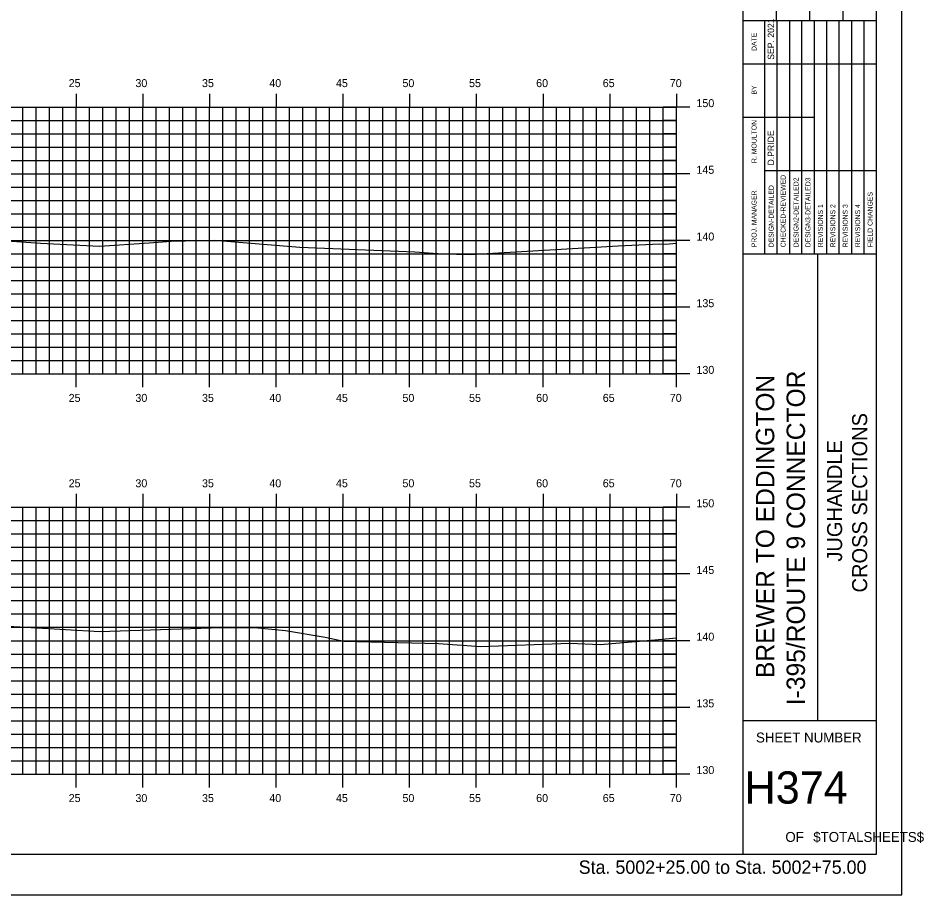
# Model space of a CAD drawing. Extents: x 851417 to 851588, y 365876 to 365986.
# Drawn here: x 851520.6 to 851588.4, y 365875.8 to 365941.5 of the extents above; entities that cross this region are included whole.
import ezdxf

# ---------------------------------------------------------------- set-up
doc = ezdxf.new("R2010")
doc.units = 0
for name, color, linetype in [('BORDER', 7, 'Continuous'), ('H_V ANNOTATION', 7, 'Continuous'), ('MAJOR', 7, 'Continuous'), ('MINOR', 7, 'Continuous'), ('PLOT BOUNDARY', 7, 'Continuous'), ('S_Roadway_Centerline', 7, 'Continuous')]:
    doc.layers.add(name, color=color, linetype=linetype)

msp = doc.modelspace()

# ---------------------------------------------------------------- linework, layer by layer
at = {"layer": 'BORDER'}
for p, q in [((851574.899, 365878.833), (851574.899, 365983.833)), ((851577.399, 365941.336), (851577.399, 365949.984)), ((851579.899, 365941.336), (851579.899, 365949.984)), ((851582.399, 365941.336), (851582.399, 365949.984)), ((851574.899, 365941.336), (851584.899, 365941.336)), ((851574.899, 365923.836), (851584.899, 365923.836)), ((851580.49, 365888.836), (851580.49, 365923.836)), ((851574.899, 365888.836), (851584.899, 365888.836))]:
    msp.add_line(p, q, dxfattribs=at)
msp.add_lwpolyline([(851424.899, 365878.833), (851584.899, 365878.833), (851584.899, 365983.833), (851424.899, 365983.833)], close=True, dxfattribs=at)
for points in [[(851576.513, 365938.086), (851576.513, 365941.336)], [(851577.446, 365923.839), (851577.446, 365941.336)], [(851578.378, 365941.336), (851578.378, 365923.839)], [(851579.309, 365923.839), (851579.309, 365941.336)], [(851580.241, 365923.839), (851580.241, 365941.336)], [(851581.173, 365923.839), (851581.173, 365941.336)], [(851582.104, 365923.839), (851582.104, 365941.336)], [(851583.036, 365923.839), (851583.036, 365941.336)], [(851583.968, 365923.839), (851583.968, 365941.336)], [(851576.514, 365923.839), (851576.514, 365940.63)], [(851574.899, 365938.086), (851584.899, 365938.086)], [(851574.899, 365934.086), (851576.514, 365934.086)], [(851576.513, 365934.086), (851580.24, 365934.086)], [(851576.513, 365930.086), (851584.899, 365930.086)]]:
    msp.add_lwpolyline(points, dxfattribs=at)
at = {"layer": 'MAJOR'}
for p, q in [((851524.898, 365935.835), (851524.898, 365934.833)), ((851529.898, 365935.835), (851529.898, 365934.833)), ((851534.898, 365935.835), (851534.898, 365934.833)), ((851539.898, 365935.835), (851539.898, 365934.833)), ((851544.898, 365935.835), (851544.898, 365934.833)), ((851549.898, 365935.835), (851549.898, 365934.833)), ((851554.898, 365935.835), (851554.898, 365934.833)), ((851559.898, 365935.835), (851559.898, 365934.833)), ((851564.898, 365935.835), (851564.898, 365934.833)), ((851569.898, 365935.835), (851569.898, 365934.833)), ((851429.898, 365934.833), (851569.898, 365934.833)), ((851429.898, 365934.833), (851569.898, 365934.833)), ((851524.898, 365914.833), (851524.898, 365934.833)), ((851529.898, 365914.833), (851529.898, 365934.833)), ((851534.898, 365914.833), (851534.898, 365934.833)), ((851539.898, 365914.833), (851539.898, 365934.833)), ((851544.898, 365914.833), (851544.898, 365934.833)), ((851549.898, 365914.833), (851549.898, 365934.833)), ((851554.898, 365914.833), (851554.898, 365934.833)), ((851559.898, 365914.833), (851559.898, 365934.833)), ((851564.898, 365914.833), (851564.898, 365934.833)), ((851570.9, 365934.833), (851568.896, 365934.833)), ((851569.898, 365914.833), (851569.898, 365934.833)), ((851569.898, 365914.833), (851569.898, 365934.833)), ((851429.898, 365929.833), (851569.898, 365929.833)), ((851570.9, 365929.833), (851568.896, 365929.833)), ((851429.898, 365924.833), (851569.898, 365924.833)), ((851570.9, 365924.833), (851568.896, 365924.833)), ((851429.898, 365919.833), (851569.898, 365919.833)), ((851570.9, 365919.833), (851568.896, 365919.833)), ((851429.898, 365914.833), (851569.898, 365914.833)), ((851429.898, 365914.833), (851569.898, 365914.833)), ((851524.898, 365913.831), (851524.898, 365914.833)), ((851529.898, 365913.831), (851529.898, 365914.833)), ((851534.898, 365913.831), (851534.898, 365914.833)), ((851539.898, 365913.831), (851539.898, 365914.833)), ((851544.898, 365913.831), (851544.898, 365914.833)), ((851549.898, 365913.831), (851549.898, 365914.833)), ((851554.898, 365913.831), (851554.898, 365914.833)), ((851559.898, 365913.831), (851559.898, 365914.833)), ((851564.898, 365913.831), (851564.898, 365914.833)), ((851570.9, 365914.833), (851568.896, 365914.833)), ((851569.898, 365913.831), (851569.898, 365914.833)), ((851524.898, 365905.835), (851524.898, 365904.833)), ((851529.898, 365905.835), (851529.898, 365904.833)), ((851534.898, 365905.835), (851534.898, 365904.833)), ((851539.898, 365905.835), (851539.898, 365904.833)), ((851544.898, 365905.835), (851544.898, 365904.833)), ((851549.898, 365905.835), (851549.898, 365904.833)), ((851554.898, 365905.835), (851554.898, 365904.833)), ((851559.898, 365905.835), (851559.898, 365904.833)), ((851564.898, 365905.835), (851564.898, 365904.833)), ((851569.898, 365905.835), (851569.898, 365904.833)), ((851429.898, 365904.833), (851569.898, 365904.833)), ((851429.898, 365904.833), (851569.898, 365904.833)), ((851524.898, 365884.833), (851524.898, 365904.833)), ((851529.898, 365884.833), (851529.898, 365904.833)), ((851534.898, 365884.833), (851534.898, 365904.833)), ((851539.898, 365884.833), (851539.898, 365904.833)), ((851544.898, 365884.833), (851544.898, 365904.833)), ((851549.898, 365884.833), (851549.898, 365904.833)), ((851554.898, 365884.833), (851554.898, 365904.833)), ((851559.898, 365884.833), (851559.898, 365904.833)), ((851564.898, 365884.833), (851564.898, 365904.833)), ((851570.9, 365904.833), (851568.896, 365904.833)), ((851569.898, 365884.833), (851569.898, 365904.833)), ((851569.898, 365884.833), (851569.898, 365904.833)), ((851429.898, 365899.833), (851569.898, 365899.833)), ((851570.9, 365899.833), (851568.896, 365899.833)), ((851429.898, 365894.833), (851569.898, 365894.833)), ((851570.9, 365894.833), (851568.896, 365894.833)), ((851429.898, 365889.833), (851569.898, 365889.833)), ((851570.9, 365889.833), (851568.896, 365889.833)), ((851429.898, 365884.833), (851569.898, 365884.833)), ((851429.898, 365884.833), (851569.898, 365884.833)), ((851524.898, 365883.831), (851524.898, 365884.833)), ((851529.898, 365883.831), (851529.898, 365884.833)), ((851534.898, 365883.831), (851534.898, 365884.833)), ((851539.898, 365883.831), (851539.898, 365884.833)), ((851544.898, 365883.831), (851544.898, 365884.833)), ((851549.898, 365883.831), (851549.898, 365884.833)), ((851554.898, 365883.831), (851554.898, 365884.833)), ((851559.898, 365883.831), (851559.898, 365884.833)), ((851564.898, 365883.831), (851564.898, 365884.833)), ((851570.9, 365884.833), (851568.896, 365884.833)), ((851569.898, 365883.831), (851569.898, 365884.833))]:
    msp.add_line(p, q, dxfattribs=at)
at = {"layer": 'MINOR'}
for p, q in [((851520.898, 365914.833), (851520.898, 365934.833)), ((851521.898, 365914.833), (851521.898, 365934.833)), ((851522.898, 365914.833), (851522.898, 365934.833)), ((851523.898, 365914.833), (851523.898, 365934.833)), ((851525.898, 365914.833), (851525.898, 365934.833)), ((851526.898, 365914.833), (851526.898, 365934.833)), ((851527.898, 365914.833), (851527.898, 365934.833)), ((851528.898, 365914.833), (851528.898, 365934.833)), ((851530.898, 365914.833), (851530.898, 365934.833)), ((851531.898, 365914.833), (851531.898, 365934.833)), ((851532.898, 365914.833), (851532.898, 365934.833)), ((851533.898, 365914.833), (851533.898, 365934.833)), ((851535.898, 365914.833), (851535.898, 365934.833)), ((851536.898, 365914.833), (851536.898, 365934.833)), ((851537.898, 365914.833), (851537.898, 365934.833)), ((851538.898, 365914.833), (851538.898, 365934.833)), ((851540.898, 365914.833), (851540.898, 365934.833)), ((851541.898, 365914.833), (851541.898, 365934.833)), ((851542.898, 365914.833), (851542.898, 365934.833)), ((851543.898, 365914.833), (851543.898, 365934.833)), ((851545.898, 365914.833), (851545.898, 365934.833)), ((851546.898, 365914.833), (851546.898, 365934.833)), ((851547.898, 365914.833), (851547.898, 365934.833)), ((851548.898, 365914.833), (851548.898, 365934.833)), ((851550.898, 365914.833), (851550.898, 365934.833)), ((851551.898, 365914.833), (851551.898, 365934.833)), ((851552.898, 365914.833), (851552.898, 365934.833)), ((851553.898, 365914.833), (851553.898, 365934.833)), ((851555.898, 365914.833), (851555.898, 365934.833)), ((851556.898, 365914.833), (851556.898, 365934.833)), ((851557.898, 365914.833), (851557.898, 365934.833)), ((851558.898, 365914.833), (851558.898, 365934.833)), ((851560.898, 365914.833), (851560.898, 365934.833)), ((851561.898, 365914.833), (851561.898, 365934.833)), ((851562.898, 365914.833), (851562.898, 365934.833)), ((851563.898, 365914.833), (851563.898, 365934.833)), ((851565.898, 365914.833), (851565.898, 365934.833)), ((851566.898, 365914.833), (851566.898, 365934.833)), ((851567.898, 365914.833), (851567.898, 365934.833)), ((851568.898, 365914.833), (851568.898, 365934.833)), ((851429.898, 365933.833), (851569.898, 365933.833)), ((851569.898, 365933.833), (851568.896, 365933.833)), ((851429.898, 365932.833), (851569.898, 365932.833)), ((851569.898, 365932.833), (851568.896, 365932.833)), ((851429.898, 365931.833), (851569.898, 365931.833)), ((851569.898, 365931.833), (851568.896, 365931.833)), ((851429.898, 365930.833), (851569.898, 365930.833)), ((851569.898, 365930.833), (851568.896, 365930.833)), ((851429.898, 365928.833), (851569.898, 365928.833)), ((851569.898, 365928.833), (851568.896, 365928.833)), ((851429.898, 365927.833), (851569.898, 365927.833)), ((851569.898, 365927.833), (851568.896, 365927.833)), ((851429.898, 365926.833), (851569.898, 365926.833)), ((851569.898, 365926.833), (851568.896, 365926.833)), ((851429.898, 365925.833), (851569.898, 365925.833)), ((851569.898, 365925.833), (851568.896, 365925.833)), ((851429.898, 365923.833), (851569.898, 365923.833)), ((851569.898, 365923.833), (851568.896, 365923.833)), ((851429.898, 365922.833), (851569.898, 365922.833)), ((851569.898, 365922.833), (851568.896, 365922.833)), ((851429.898, 365921.833), (851569.898, 365921.833)), ((851569.898, 365921.833), (851568.896, 365921.833)), ((851429.898, 365920.833), (851569.898, 365920.833)), ((851569.898, 365920.833), (851568.896, 365920.833)), ((851429.898, 365918.833), (851569.898, 365918.833)), ((851569.898, 365918.833), (851568.896, 365918.833)), ((851429.898, 365917.833), (851569.898, 365917.833)), ((851569.898, 365917.833), (851568.896, 365917.833)), ((851429.898, 365916.833), (851569.898, 365916.833)), ((851569.898, 365916.833), (851568.896, 365916.833)), ((851429.898, 365915.833), (851569.898, 365915.833)), ((851569.898, 365915.833), (851568.896, 365915.833)), ((851520.898, 365884.833), (851520.898, 365904.833)), ((851521.898, 365884.833), (851521.898, 365904.833)), ((851522.898, 365884.833), (851522.898, 365904.833)), ((851523.898, 365884.833), (851523.898, 365904.833)), ((851525.898, 365884.833), (851525.898, 365904.833)), ((851526.898, 365884.833), (851526.898, 365904.833)), ((851527.898, 365884.833), (851527.898, 365904.833)), ((851528.898, 365884.833), (851528.898, 365904.833)), ((851530.898, 365884.833), (851530.898, 365904.833)), ((851531.898, 365884.833), (851531.898, 365904.833)), ((851532.898, 365884.833), (851532.898, 365904.833)), ((851533.898, 365884.833), (851533.898, 365904.833)), ((851535.898, 365884.833), (851535.898, 365904.833)), ((851536.898, 365884.833), (851536.898, 365904.833)), ((851537.898, 365884.833), (851537.898, 365904.833)), ((851538.898, 365884.833), (851538.898, 365904.833)), ((851540.898, 365884.833), (851540.898, 365904.833)), ((851541.898, 365884.833), (851541.898, 365904.833)), ((851542.898, 365884.833), (851542.898, 365904.833)), ((851543.898, 365884.833), (851543.898, 365904.833)), ((851545.898, 365884.833), (851545.898, 365904.833)), ((851546.898, 365884.833), (851546.898, 365904.833)), ((851547.898, 365884.833), (851547.898, 365904.833)), ((851548.898, 365884.833), (851548.898, 365904.833)), ((851550.898, 365884.833), (851550.898, 365904.833)), ((851551.898, 365884.833), (851551.898, 365904.833)), ((851552.898, 365884.833), (851552.898, 365904.833)), ((851553.898, 365884.833), (851553.898, 365904.833)), ((851555.898, 365884.833), (851555.898, 365904.833)), ((851556.898, 365884.833), (851556.898, 365904.833)), ((851557.898, 365884.833), (851557.898, 365904.833)), ((851558.898, 365884.833), (851558.898, 365904.833)), ((851560.898, 365884.833), (851560.898, 365904.833)), ((851561.898, 365884.833), (851561.898, 365904.833)), ((851562.898, 365884.833), (851562.898, 365904.833)), ((851563.898, 365884.833), (851563.898, 365904.833)), ((851565.898, 365884.833), (851565.898, 365904.833)), ((851566.898, 365884.833), (851566.898, 365904.833)), ((851567.898, 365884.833), (851567.898, 365904.833)), ((851568.898, 365884.833), (851568.898, 365904.833)), ((851429.898, 365903.833), (851569.898, 365903.833)), ((851569.898, 365903.833), (851568.896, 365903.833)), ((851429.898, 365902.833), (851569.898, 365902.833)), ((851569.898, 365902.833), (851568.896, 365902.833)), ((851429.898, 365901.833), (851569.898, 365901.833)), ((851569.898, 365901.833), (851568.896, 365901.833)), ((851429.898, 365900.833), (851569.898, 365900.833)), ((851569.898, 365900.833), (851568.896, 365900.833)), ((851429.898, 365898.833), (851569.898, 365898.833)), ((851569.898, 365898.833), (851568.896, 365898.833)), ((851429.898, 365897.833), (851569.898, 365897.833)), ((851569.898, 365897.833), (851568.896, 365897.833)), ((851429.898, 365896.833), (851569.898, 365896.833)), ((851569.898, 365896.833), (851568.896, 365896.833)), ((851429.898, 365895.833), (851569.898, 365895.833)), ((851569.898, 365895.833), (851568.896, 365895.833)), ((851429.898, 365893.833), (851569.898, 365893.833)), ((851569.898, 365893.833), (851568.896, 365893.833)), ((851429.898, 365892.833), (851569.898, 365892.833)), ((851569.898, 365892.833), (851568.896, 365892.833)), ((851429.898, 365891.833), (851569.898, 365891.833)), ((851569.898, 365891.833), (851568.896, 365891.833)), ((851429.898, 365890.833), (851569.898, 365890.833)), ((851569.898, 365890.833), (851568.896, 365890.833)), ((851429.898, 365888.833), (851569.898, 365888.833)), ((851569.898, 365888.833), (851568.896, 365888.833)), ((851429.898, 365887.833), (851569.898, 365887.833)), ((851569.898, 365887.833), (851568.896, 365887.833)), ((851429.898, 365886.833), (851569.898, 365886.833)), ((851569.898, 365886.833), (851568.896, 365886.833)), ((851429.898, 365885.833), (851569.898, 365885.833)), ((851569.898, 365885.833), (851568.896, 365885.833))]:
    msp.add_line(p, q, dxfattribs=at)
at = {"layer": 'PLOT BOUNDARY'}
msp.add_lwpolyline([(851416.805, 365875.774), (851586.805, 365875.774), (851586.805, 365985.774), (851416.805, 365985.774)], close=True, dxfattribs=at)
at = {"layer": 'S_Roadway_Centerline'}
for points in [[(851512.576, 365925.296), (851522.222, 365924.635), (851526.656, 365924.406), (851530.376, 365924.664), (851532.03, 365924.787), (851535.275, 365924.859), (851541.665, 365924.333), (851550.292, 365923.983), (851552.377, 365923.84), (851554.45, 365923.794), (851565.535, 365924.426), (851568.619, 365924.574), (851569.089, 365924.547), (851569.898, 365924.63)], [(851518.942, 365895.978), (851526.681, 365895.522), (851535.764, 365895.81), (851538.282, 365895.829), (851540.598, 365895.593), (851543.577, 365895.088), (851544.971, 365894.784), (851552.056, 365894.622), (851555.229, 365894.398), (851561.91, 365894.649), (851564.172, 365894.54), (851567.993, 365894.878), (851569.898, 365895.044)]]:
    msp.add_lwpolyline(points, dxfattribs=at)

# ---------------------------------------------------------------- texts
at = {"layer": 'BORDER'}
for s, height, p in [('SEP. 2021', 0.4845, (851577.222, 365938.382)), ('DATE', 0.3714, (851575.903, 365939.042)), ('BY', 0.3714, (851575.903, 365935.771)), ('R. MOULTON', 0.3727, (851575.903, 365930.639)), ('D.PRIDE', 0.4845, (851577.222, 365930.459)), ('CHECKED-REVIEWED', 0.37275, (851578.08, 365924.324)), ('DESIGN-DETAILED', 0.37275, (851577.185, 365924.324)), ('DESIGN2-DETAILED2', 0.37275, (851579.049, 365924.324)), ('DESIGN3-DETAILED3', 0.37275, (851579.943, 365924.324)), ('PROJ. MANAGER', 0.37275, (851575.903, 365924.324)), ('FIELD CHANGES', 0.37275, (851584.601, 365924.324)), ('REVISIONS 4', 0.37275, (851583.67, 365924.324)), ('REVISIONS 1', 0.37275, (851580.875, 365924.324)), ('REVISIONS 2', 0.37275, (851581.806, 365924.324)), ('REVISIONS 3', 0.37275, (851582.738, 365924.324)), ('BREWER TO EDDINGTON', 1.37787, (851577.233, 365892.038)), ('I-395/ROUTE 9 CONNECTOR', 1.37787, (851579.534, 365889.998)), ('CROSS SECTIONS', 1.125, (851584.196, 365898.444)), ('JUGHANDLE', 1.125, (851582.317, 365900.756))]:
    msp.add_text(s, height=height, rotation=90, dxfattribs=at).set_placement(p)
for s, height, p in [('SHEET NUMBER', 0.74527, (851575.864, 365887.2)), ('H374', 2.4194, (851575.004, 365882.616)), ('OF', 0.7453, (851578.066, 365879.746)), ('$TOTALSHEETS$', 0.74527, (851580.155, 365879.746))]:
    msp.add_text(s, height=height, dxfattribs=at).set_placement(p)
at = {"layer": 'H_V ANNOTATION'}
for s, height, p in [('25', 0.6, (851524.344, 365936.333)), ('30', 0.6, (851529.347, 365936.333)), ('35', 0.6, (851534.339, 365936.333)), ('40', 0.6, (851539.385, 365936.333)), ('50', 0.6, (851549.363, 365936.333)), ('60', 0.6, (851559.385, 365936.333)), ('65', 0.6, (851564.377, 365936.333)), ('70', 0.6, (851569.4, 365936.333)), ('45', 0.6, (851544.377, 365936.333)), ('55', 0.6, (851554.355, 365936.333)), ('150', 0.6, (851571.398, 365934.833)), ('145', 0.6, (851571.398, 365929.833)), ('140', 0.6, (851571.398, 365924.833)), ('135', 0.6, (851571.398, 365919.833)), ('130', 0.6, (851571.398, 365914.833)), ('25', 0.6, (851524.344, 365912.733)), ('30', 0.6, (851529.347, 365912.733)), ('35', 0.6, (851534.339, 365912.733)), ('40', 0.6, (851539.385, 365912.733)), ('45', 0.6, (851544.377, 365912.733)), ('50', 0.6, (851549.363, 365912.733)), ('55', 0.6, (851554.355, 365912.733)), ('60', 0.6, (851559.385, 365912.733)), ('65', 0.6, (851564.377, 365912.733)), ('70', 0.6, (851569.4, 365912.733)), ('25', 0.6, (851524.344, 365906.333)), ('30', 0.6, (851529.347, 365906.333)), ('35', 0.6, (851534.339, 365906.333)), ('40', 0.6, (851539.385, 365906.333)), ('45', 0.6, (851544.377, 365906.333)), ('50', 0.6, (851549.363, 365906.333)), ('55', 0.6, (851554.355, 365906.333)), ('60', 0.6, (851559.385, 365906.333)), ('65', 0.6, (851564.377, 365906.333)), ('70', 0.6, (851569.4, 365906.333)), ('150', 0.6, (851571.398, 365904.833)), ('145', 0.6, (851571.398, 365899.833)), ('140', 0.6, (851571.398, 365894.833)), ('135', 0.6, (851571.398, 365889.833)), ('130', 0.6, (851571.398, 365884.833)), ('25', 0.6, (851524.344, 365882.733)), ('30', 0.6, (851529.347, 365882.733)), ('35', 0.6, (851534.339, 365882.733)), ('40', 0.6, (851539.385, 365882.733)), ('45', 0.6, (851544.377, 365882.733)), ('50', 0.6, (851549.363, 365882.733)), ('55', 0.6, (851554.355, 365882.733)), ('60', 0.6, (851559.385, 365882.733)), ('65', 0.6, (851564.377, 365882.733)), ('70', 0.6, (851569.4, 365882.733)), ('Sta. 5002+25.00 to Sta. 5002+75.00', 1.0002, (851562.575, 365877.353))]:
    msp.add_text(s, height=height, dxfattribs=at).set_placement(p)

doc.saveas('drawing.dxf')
